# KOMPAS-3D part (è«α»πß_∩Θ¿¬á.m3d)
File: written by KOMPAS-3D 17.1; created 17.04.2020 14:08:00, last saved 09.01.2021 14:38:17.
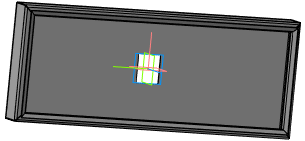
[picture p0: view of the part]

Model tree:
1. Эскиз:1
2. Листовое тело:1
     Расстояние 1 = 10; Радиус сгиба = 5
3. горизонтальные
     Радиус сгиба = 1.5; Коэффициент = 0.4; Величина сгиба = 10; Радиус сгиба = 1.5; Коэффициент = 0.4; Величина сгиба = 10; Радиус сгиба = 1.5; Толщина листового тела = 1.5; Ширина освобождения сгиба = 3; Ширина сгиба = 500; Длина 2 = 10
4. вертикальные
     Радиус сгиба = 1.5; Коэффициент = 0.4; Величина сгиба = 10; Радиус сгиба = 1.5; Коэффициент = 0.4; Величина сгиба = 10; Радиус сгиба = 1.5; Толщина листового тела = 1.5; Ширина освобождения сгиба = 3; Ширина сгиба = 194; Длина 1 = 1.5; Длина 2 = 1.5; Длина 2 = 10
5. Сгиб:2
     Радиус сгиба = 2; Коэффициент = 0.4; Величина сгиба = 10; Радиус сгиба = 2; Коэффициент = 0.4; Величина сгиба = 10; Радиус сгиба = 2; Коэффициент = 0.4; Величина сгиба = 10; Радиус сгиба = 2; Коэффициент = 0.4; Величина сгиба = 10; Радиус сгиба = 2; Толщина листового тела = 1.5; Ширина освобождения сгиба = 3; Ширина сгиба = 500; Угол на сгибе 1 = 40; Уклон 1 = 45; Длина 1 = 10; Угол на сгибе 2 = 40; Уклон 2 = 45; Длина 2 = 10
6. Сгиб:3
     Радиус сгиба = 2; Коэффициент = 0.4; Величина сгиба = 10; Радиус сгиба = 2; Коэффициент = 0.4; Величина сгиба = 10; Радиус сгиба = 2; Коэффициент = 0.4; Величина сгиба = 10; Радиус сгиба = 2; Коэффициент = 0.4; Величина сгиба = 10; Радиус сгиба = 2; Толщина листового тела = 1.5; Угол сгиба = 150; Ширина освобождения сгиба = 3; Ширина сгиба = 473.146; Угол на сгибе 1 = 10; Уклон 1 = -40; Длина 1 = 8; Угол на сгибе 2 = 10; Уклон 2 = -40; Длина 2 = 10

Expressions: l/2; w/2; window_l/2; window_w/2
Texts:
  ex71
